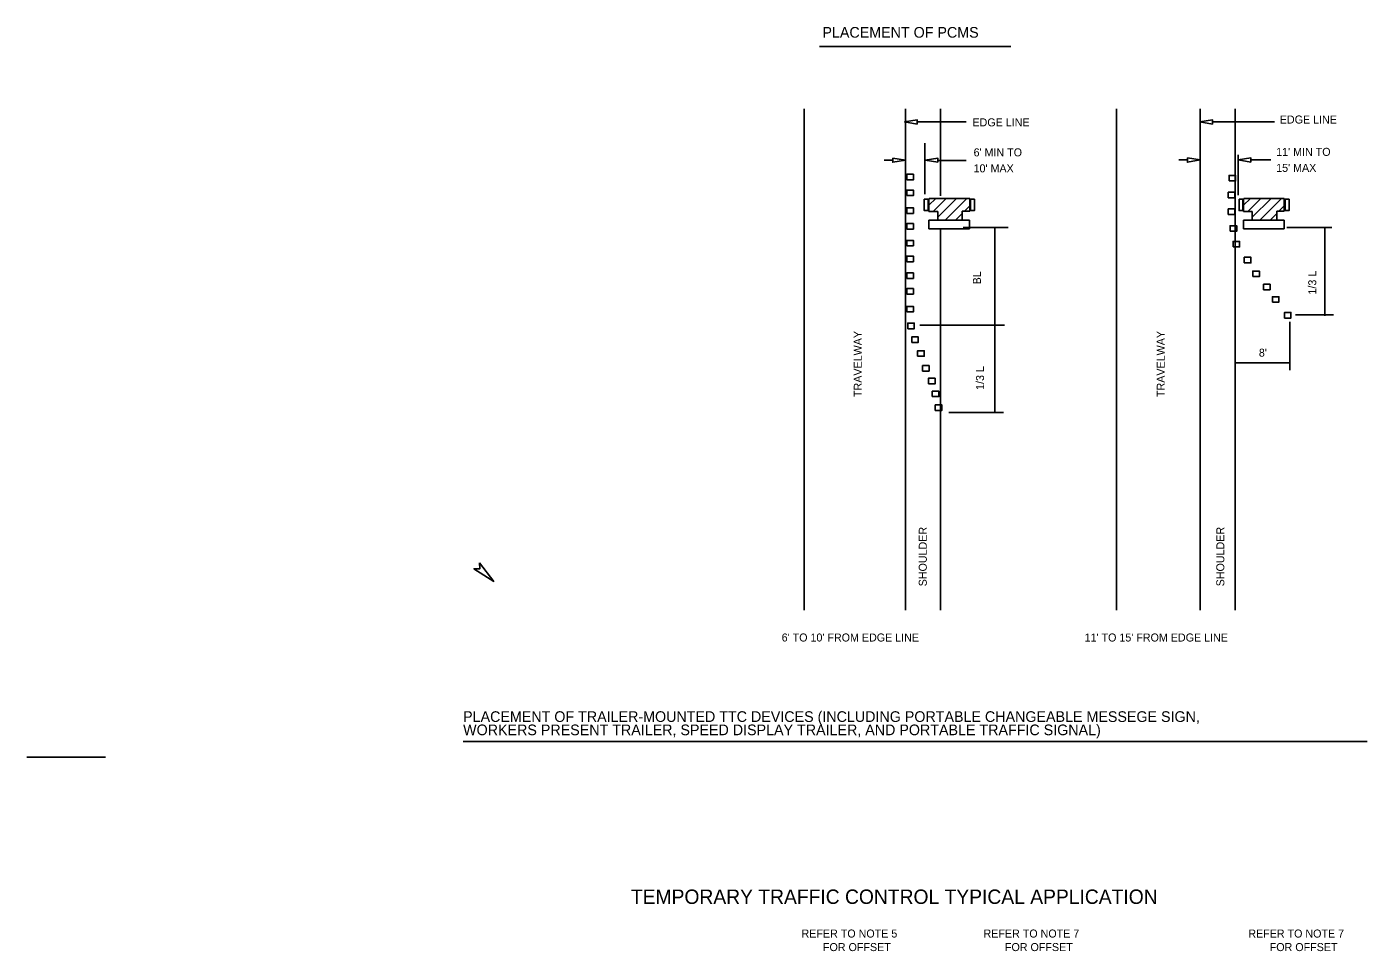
# Model space of a CAD drawing. Extents: x 9 to 25.8, y 6 to 22.7.
# Drawn here: x 9.05 to 19.44, y 15.53 to 22.7 of the extents above; entities that cross this region are included whole.
import ezdxf

# ---------------------------------------------------------------- set-up
doc = ezdxf.new("R2010")
doc.units = 0
for name, color, linetype in [('Default', 7, 'Continuous'), ('DETL-DIMS', 7, 'Continuous'), ('DETL-LINE', 7, 'Continuous'), ('DETL-NOTE', 7, 'Continuous'), ('DETL-TITL', 7, 'Continuous')]:
    doc.layers.add(name, color=color, linetype=linetype)

msp = doc.modelspace()

# ---------------------------------------------------------------- linework, layer by layer
at = {"layer": 'Default'}
msp.add_line((9.656, 17.034), (9.046, 17.034), dxfattribs=at)
at = {"layer": 'DETL-DIMS'}
for p, q in [((15.948, 21.964), (16.33, 21.964)), ((18.239, 21.964), (18.72, 21.964)), ((16.01, 21.401), (16.01, 21.798)), ((15.76, 21.666), (15.693, 21.666)), ((16.109, 21.664), (16.329, 21.664)), ((18.045, 21.667), (17.978, 21.667)), ((18.439, 21.393), (18.439, 21.706)), ((18.536, 21.668), (18.692, 21.668)), ((16.305, 21.142), (16.654, 21.142)), ((16.551, 21.142), (16.551, 19.703)), ((18.815, 21.142), (19.165, 21.142)), ((19.11, 21.142), (19.11, 20.459)), ((15.971, 20.386), (16.626, 20.386)), ((16.245, 20.386), (16.245, 20.386)), ((18.839, 20.41), (18.839, 20.037)), ((18.883, 20.465), (19.177, 20.465)), ((18.414, 20.092), (18.839, 20.092)), ((16.195, 19.709), (16.618, 19.709)), ((12.666, 18.397), (12.556, 18.541)), ((12.556, 18.541), (12.559, 18.495)), ((12.666, 18.397), (12.513, 18.495)), ((12.559, 18.495), (12.513, 18.495))]:
    msp.add_line(p, q, dxfattribs=at)
for points in [[(15.95, 21.946), (15.95, 21.978), (15.852, 21.962)], [(18.24, 21.946), (18.24, 21.978), (18.142, 21.962)], [(15.76, 21.682), (15.76, 21.65), (15.858, 21.666)], [(16.109, 21.65), (16.109, 21.682), (16.011, 21.666)], [(18.045, 21.683), (18.045, 21.65), (18.143, 21.667)], [(18.537, 21.65), (18.537, 21.683), (18.439, 21.667)], [(12.556, 18.541), (12.666, 18.397), (12.513, 18.495), (12.559, 18.495)]]:
    msp.add_lwpolyline(points, close=True, dxfattribs=at)
at = {"layer": 'DETL-LINE'}
for p, q in [((15.074, 22.065), (15.074, 18.175)), ((15.858, 22.065), (15.858, 18.175)), ((16.13, 22.065), (16.13, 21.389)), ((17.495, 22.065), (17.495, 18.175)), ((18.143, 22.065), (18.143, 18.175)), ((18.414, 22.065), (18.414, 18.175)), ((16.005, 21.274), (16.005, 21.362)), ((16.005, 21.362), (16.036, 21.362)), ((16.036, 21.362), (16.036, 21.274)), ((16.041, 21.316), (16.094, 21.369)), ((16.041, 21.268), (16.041, 21.369)), ((16.042, 21.369), (16.357, 21.369)), ((16.074, 21.268), (16.174, 21.369)), ((16.109, 21.223), (16.254, 21.369)), ((16.166, 21.201), (16.334, 21.369)), ((16.316, 21.27), (16.357, 21.311)), ((16.357, 21.369), (16.357, 21.27)), ((16.362, 21.362), (16.393, 21.362)), ((16.362, 21.274), (16.362, 21.362)), ((16.393, 21.362), (16.393, 21.274)), ((18.445, 21.274), (18.445, 21.362)), ((18.445, 21.362), (18.475, 21.362)), ((18.475, 21.362), (18.475, 21.274)), ((18.48, 21.316), (18.533, 21.369)), ((18.48, 21.268), (18.48, 21.369)), ((18.482, 21.369), (18.796, 21.369)), ((18.513, 21.268), (18.613, 21.369)), ((18.548, 21.223), (18.694, 21.369)), ((18.606, 21.201), (18.774, 21.369)), ((18.755, 21.27), (18.796, 21.311)), ((18.796, 21.369), (18.796, 21.27)), ((18.802, 21.362), (18.833, 21.362)), ((18.802, 21.274), (18.802, 21.362)), ((18.833, 21.362), (18.833, 21.274)), ((16.036, 21.274), (16.005, 21.274)), ((16.109, 21.268), (16.041, 21.268)), ((16.109, 21.2), (16.109, 21.268)), ((16.247, 21.201), (16.298, 21.252)), ((16.298, 21.27), (16.298, 21.2)), ((16.357, 21.27), (16.298, 21.27)), ((16.393, 21.274), (16.362, 21.274)), ((18.475, 21.274), (18.445, 21.274)), ((18.548, 21.268), (18.48, 21.268)), ((18.548, 21.2), (18.548, 21.268)), ((18.686, 21.201), (18.737, 21.252)), ((18.737, 21.27), (18.737, 21.2)), ((18.796, 21.27), (18.737, 21.27)), ((18.833, 21.274), (18.802, 21.274)), ((16.041, 21.134), (16.041, 21.2)), ((16.041, 21.2), (16.355, 21.2)), ((16.355, 21.134), (16.041, 21.134)), ((16.13, 21.126), (16.13, 18.175)), ((16.355, 21.2), (16.355, 21.134)), ((18.48, 21.134), (18.48, 21.2)), ((18.48, 21.2), (18.795, 21.2)), ((18.795, 21.134), (18.48, 21.134)), ((18.795, 21.2), (18.795, 21.134)), ((15.914, 20.386), (15.914, 20.386))]:
    msp.add_line(p, q, dxfattribs=at)
for points in [[(15.869, 21.513), (15.869, 21.556), (15.92, 21.556), (15.92, 21.513)], [(18.368, 21.504), (18.368, 21.547), (18.419, 21.547), (18.419, 21.504)], [(15.869, 21.391), (15.869, 21.433), (15.92, 21.433), (15.92, 21.391)], [(18.361, 21.374), (18.361, 21.417), (18.412, 21.417), (18.412, 21.374)], [(16.005, 21.362), (16.036, 21.362), (16.036, 21.274), (16.005, 21.274)], [(16.362, 21.362), (16.393, 21.362), (16.393, 21.274), (16.362, 21.274)], [(18.445, 21.362), (18.475, 21.362), (18.475, 21.274), (18.445, 21.274)], [(18.802, 21.362), (18.833, 21.362), (18.833, 21.274), (18.802, 21.274)], [(15.869, 21.253), (15.869, 21.296), (15.92, 21.296), (15.92, 21.253)], [(18.361, 21.244), (18.361, 21.287), (18.412, 21.287), (18.412, 21.244)], [(15.869, 21.131), (15.869, 21.173), (15.92, 21.173), (15.92, 21.131)], [(16.355, 21.2), (16.041, 21.2), (16.041, 21.134), (16.355, 21.134)], [(18.376, 21.114), (18.376, 21.157), (18.427, 21.157), (18.427, 21.114)], [(18.795, 21.2), (18.48, 21.2), (18.48, 21.134), (18.795, 21.134)], [(15.869, 21.001), (15.869, 21.043), (15.92, 21.043), (15.92, 21.001)], [(18.399, 20.992), (18.399, 21.035), (18.45, 21.035), (18.45, 20.992)], [(15.869, 20.878), (15.869, 20.921), (15.92, 20.921), (15.92, 20.878)], [(18.486, 20.869), (18.486, 20.912), (18.537, 20.912), (18.537, 20.869)], [(15.869, 20.748), (15.869, 20.791), (15.92, 20.791), (15.92, 20.748)], [(18.552, 20.762), (18.552, 20.805), (18.603, 20.805), (18.603, 20.762)], [(18.635, 20.66), (18.635, 20.703), (18.686, 20.703), (18.686, 20.66)], [(15.869, 20.626), (15.869, 20.669), (15.92, 20.669), (15.92, 20.626)], [(18.704, 20.564), (18.704, 20.606), (18.755, 20.606), (18.755, 20.564)], [(15.869, 20.488), (15.869, 20.531), (15.92, 20.531), (15.92, 20.488)], [(18.798, 20.441), (18.798, 20.484), (18.848, 20.484), (18.848, 20.441)], [(15.877, 20.358), (15.877, 20.401), (15.927, 20.401), (15.927, 20.358)], [(15.907, 20.251), (15.907, 20.294), (15.958, 20.294), (15.958, 20.251)], [(15.953, 20.144), (15.953, 20.187), (16.004, 20.187), (16.004, 20.144)], [(15.991, 20.029), (15.991, 20.072), (16.042, 20.072), (16.042, 20.029)], [(16.037, 19.93), (16.037, 19.973), (16.088, 19.973), (16.088, 19.93)], [(16.067, 19.831), (16.067, 19.873), (16.118, 19.873), (16.118, 19.831)], [(16.09, 19.724), (16.09, 19.766), (16.141, 19.766), (16.141, 19.724)]]:
    msp.add_lwpolyline(points, close=True, dxfattribs=at)
at = {"layer": 'DETL-NOTE'}
for p, q in [((15.191, 22.548), (16.676, 22.548)), ((12.429, 17.154), (19.439, 17.154))]:
    msp.add_line(p, q, dxfattribs=at)

# ---------------------------------------------------------------- texts
for s, height, p in [('PLACEMENT OF PCMS', 0.08276, (15.215, 22.616)), ('EDGE LINE', 0.0621, (16.378, 21.928)), ('EDGE LINE', 0.0621, (18.761, 21.95)), ("6' MIN TO", 0.0621, (16.387, 21.695)), ("11' MIN TO", 0.0621, (18.733, 21.699)), ("10' MAX", 0.0621, (16.387, 21.571)), ("15' MAX", 0.0621, (18.733, 21.575)), ("8'", 0.0621, (18.599, 20.141)), ("6' TO 10' FROM EDGE LINE", 0.06207, (14.899, 17.931)), ("11' TO 15' FROM EDGE LINE", 0.06207, (17.248, 17.931)), ('PLACEMENT OF TRAILER-MOUNTED TTC DEVICES (INCLUDING PORTABLE CHANGEABLE MESSEGE SIGN, ', 0.08276, (12.429, 17.307)), ('WORKERS PRESENT TRAILER, SPEED DISPLAY TRAILER, AND PORTABLE TRAFFIC SIGNAL)', 0.08276, (12.429, 17.204)), ('REFER TO NOTE 5', 0.06207, (15.053, 15.634)), ('REFER TO NOTE 7', 0.06207, (16.464, 15.634)), ('REFER TO NOTE 7', 0.06207, (18.517, 15.634)), ('FOR OFFSET', 0.0621, (15.219, 15.529)), ('FOR OFFSET', 0.0621, (16.63, 15.529)), ('FOR OFFSET', 0.0621, (18.683, 15.529))]:
    msp.add_text(s, height=height, dxfattribs=at).set_placement(p)
for s, p in [('BL', (16.444, 20.702)), ('1/3 L', (19.044, 20.623)), ('TRAVELWAY', (15.52, 19.828)), ('TRAVELWAY', (17.869, 19.828)), ('1/3 L', (16.468, 19.883)), ('SHOULDER', (16.024, 18.359)), ('SHOULDER', (18.331, 18.359))]:
    msp.add_text(s, height=0.0621, rotation=90, dxfattribs=at).set_placement(p)
at = {"layer": 'DETL-TITL'}
msp.add_text('TEMPORARY TRAFFIC CONTROL TYPICAL APPLICATION', height=0.11172, dxfattribs=at).set_placement((13.73, 15.895))

doc.saveas('drawing.dxf')
